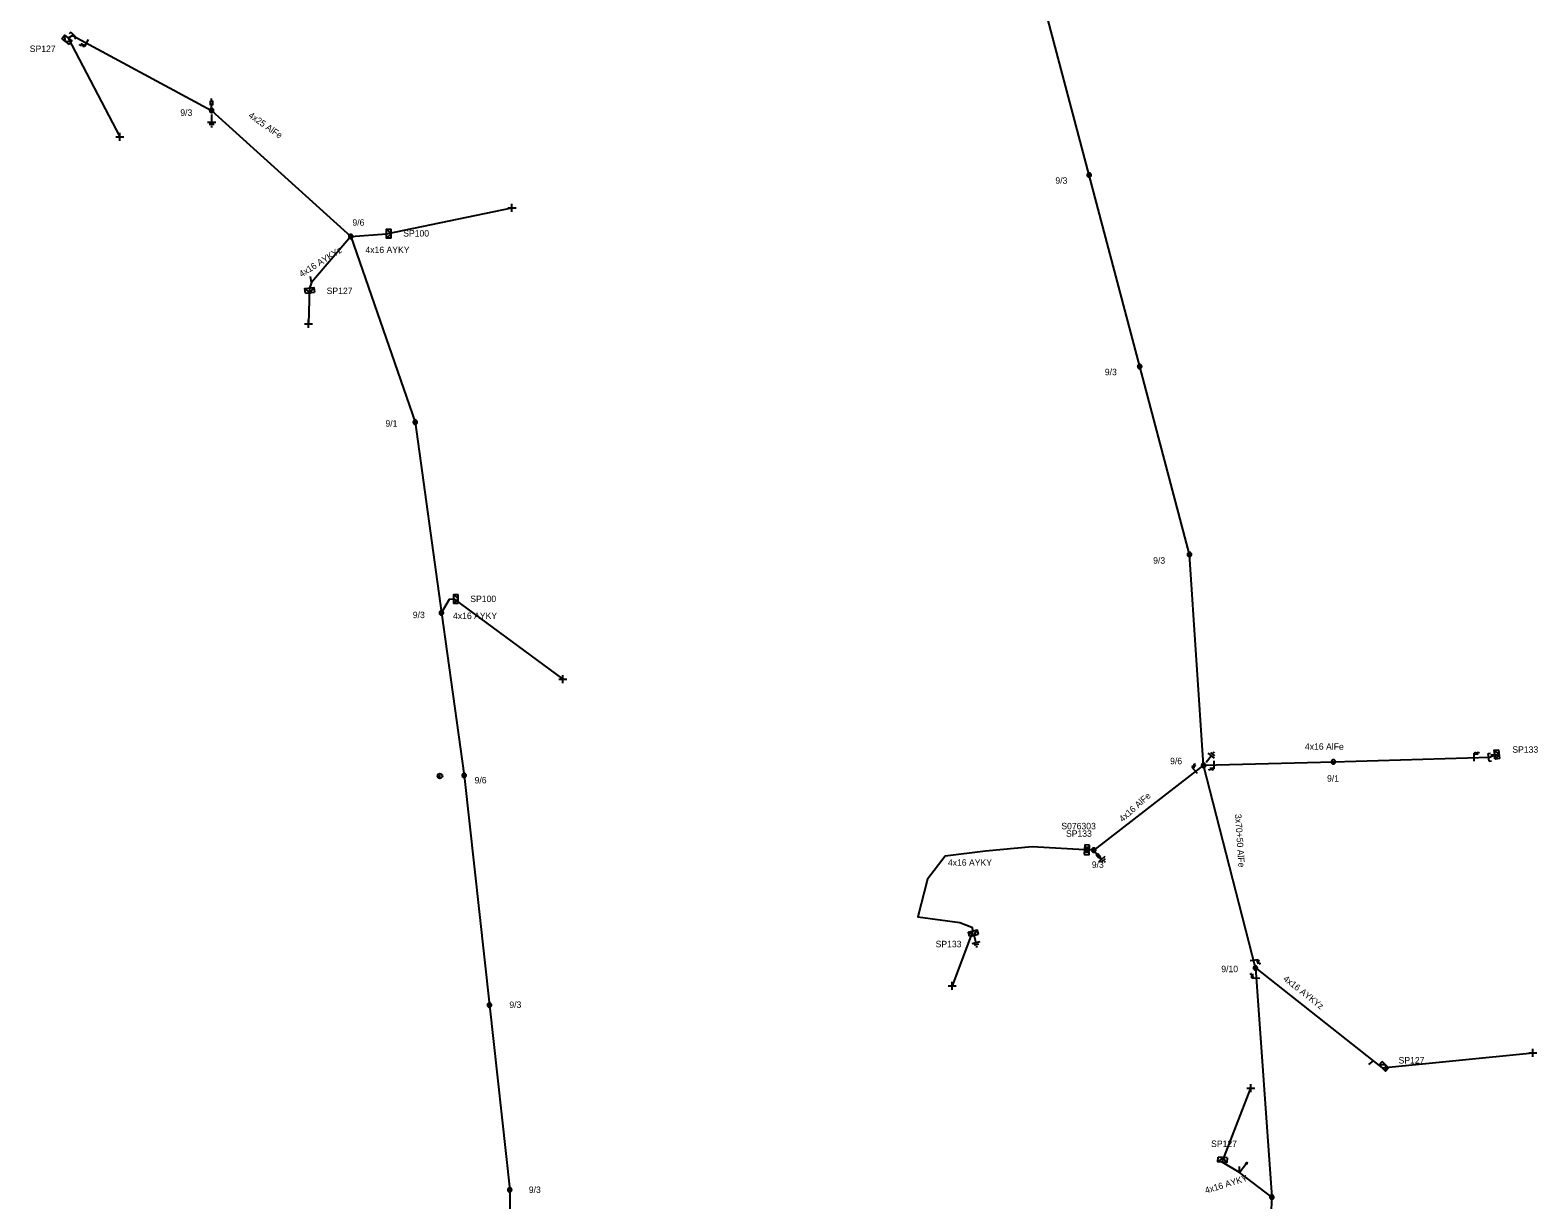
# Model space of a CAD drawing. Extents: x -717562 to -713845, y -1151196 to -1143903.
# Drawn here: x -714412.7 to -714178.8, y -1146157.4 to -1145975.9 of the extents above; entities that cross this region are included whole.
import ezdxf

# ---------------------------------------------------------------- set-up
doc = ezdxf.new("R2010")
doc.units = 0
for name, color, linetype in [('Vrstva 1', 7, 'Continuous'), ('Vrstva 10', 7, 'Continuous'), ('Vrstva 12', 7, 'Continuous'), ('Vrstva 13', 7, 'Continuous'), ('Vrstva 14', 7, 'Continuous'), ('Vrstva 15', 7, 'Continuous'), ('Vrstva 16', 7, 'Continuous'), ('Vrstva 18', 7, 'Continuous'), ('Vrstva 2', 7, 'Continuous'), ('Vrstva 28', 7, 'Continuous'), ('Vrstva 29', 7, 'Continuous'), ('Vrstva 30', 7, 'Continuous'), ('Vrstva 31', 7, 'Continuous'), ('Vrstva 33', 7, 'Continuous'), ('Vrstva 34', 7, 'Continuous'), ('Vrstva 36', 7, 'Continuous'), ('Vrstva 4', 7, 'Continuous'), ('Vrstva 5', 7, 'Continuous'), ('Vrstva 52', 7, 'Continuous'), ('Vrstva 53', 7, 'Continuous'), ('Vrstva 54', 7, 'Continuous'), ('Vrstva 55', 7, 'Continuous'), ('Vrstva 59', 7, 'Continuous'), ('Vrstva 6', 7, 'Continuous'), ('Vrstva 8', 7, 'Continuous'), ('Vrstva 9', 7, 'Continuous')]:
    doc.layers.add(name, color=color, linetype=linetype)

# ---------------------------------------------------------------- blocks, each defined once
blk = doc.blocks.new('NN440')
at = {"layer": 'Vrstva 2'}
for points in [[(0.63, 0), (0.63, 0.06), (0.62, 0.13), (0.6, 0.19), (0.58, 0.25), (0.55, 0.31), (0.51, 0.37), (0.47, 0.42), (0.42, 0.46), (0.37, 0.51), (0.32, 0.54), (0.26, 0.57), (0.2, 0.59), (0.13, 0.61), (0.07, 0.62), (0, 0.63), (-0.06, 0.62), (-0.13, 0.61), (-0.19, 0.59), (-0.26, 0.57), (-0.31, 0.54), (-0.37, 0.51), (-0.42, 0.46), (-0.47, 0.42), (-0.51, 0.37), (-0.54, 0.31), (-0.57, 0.25), (-0.6, 0.19), (-0.62, 0.13), (-0.63, 0.06), (-0.63, 0), (-0.63, -0.07), (-0.62, -0.14), (-0.6, -0.2), (-0.57, -0.26), (-0.54, -0.32), (-0.51, -0.37), (-0.47, -0.43), (-0.42, -0.47), (-0.37, -0.51), (-0.31, -0.55), (-0.26, -0.58), (-0.19, -0.6), (-0.13, -0.62), (-0.06, -0.63), (0, -0.63), (0.07, -0.63), (0.13, -0.62), (0.2, -0.6), (0.26, -0.58), (0.32, -0.55), (0.37, -0.51), (0.42, -0.47), (0.47, -0.43), (0.51, -0.37), (0.55, -0.32), (0.58, -0.26), (0.6, -0.2), (0.62, -0.14), (0.63, -0.07), (0.63, 0)], [(-0.63, 0), (0.63, 0)], [(-0.6, -0.18), (0.57, -0.18)], [(-0.51, -0.32), (0.5, -0.32)], [(-0.37, -0.47), (0.35, -0.47)]]:
    blk.add_lwpolyline(points, dxfattribs=at)
blk = doc.blocks.new('NN560')
at = {"layer": 'Vrstva 2'}
for points in [[(2, 0), (1.59, 0.14)], [(0, 0), (2, 0)], [(2, 0), (1.59, -0.13)]]:
    blk.add_lwpolyline(points, dxfattribs=at)
blk = doc.blocks.new('NN840')
at = {"layer": 'Vrstva 15'}
for points in [[(0, 0.62), (0, -0.63)], [(-0.75, -0.71), (-0.75, -0.66)], [(-0.73, -0.76), (-0.75, -0.71)], [(-0.66, -0.8), (-0.73, -0.76)], [(-0.63, -0.8), (-0.66, -0.8)], [(-0.56, -0.76), (-0.63, -0.8)], [(-0.54, -0.71), (-0.56, -0.76)], [(-0.54, -0.38), (-0.54, -0.71)], [(-0.33, -0.38), (-0.33, -0.8)], [(-0.33, -0.64), (-0.13, -0.38)], [(-0.26, -0.56), (-0.09, -0.8)]]:
    blk.add_lwpolyline(points, dxfattribs=at)
blk = doc.blocks.new('NN770')
at = {"layer": 'Vrstva 10'}
for p, q in [((0, 0.19), (0, 0.26)), ((0, -0.28), (0, 0.11))]:
    blk.add_line(p, q, dxfattribs=at)
blk.add_circle((0, -0.01), 0.375, dxfattribs=at)
blk = doc.blocks.new('NN800')
at = {"layer": 'Vrstva 1'}
for points in [[(-0.44, 0.44), (0.44, -0.44)], [(-0.44, -0.44), (0.44, 0.44)]]:
    blk.add_lwpolyline(points, dxfattribs=at)
blk = doc.blocks.new('NN820')
at = {"layer": 'Vrstva 13'}
for points in [[(0, 0), (0, -1.05)], [(-0.16, -0.81), (0.16, -0.81)], [(-0.16, -1.47), (-0.16, -0.81)], [(0.16, -1.47), (-0.16, -1.47)], [(0, -1.05), (-0.06, -0.93)], [(0, -1.05), (0.06, -0.93)], [(0, -1.47), (0, -1.87)], [(0.16, -0.81), (0.16, -1.47)]]:
    blk.add_lwpolyline(points, dxfattribs=at)
blk = doc.blocks.new('NN620')
at = {"layer": 'Vrstva 8'}
for points in [[(0.75, 0), (-0.75, 0)], [(-0.75, 0), (-0.75, -0.75)], [(0.75, -0.75), (0.75, 0)], [(-0.75, -0.75), (0.75, -0.75)], [(0.37, -0.18), (-0.38, -0.18)], [(-0.38, -0.18), (-0.38, -0.56)], [(-0.38, -0.56), (0.37, -0.56)], [(0.32, -0.23), (-0.33, -0.23)], [(-0.33, -0.23), (-0.33, -0.51)], [(-0.33, -0.51), (0.32, -0.51)], [(0.27, -0.27), (-0.28, -0.27)], [(-0.28, -0.27), (-0.28, -0.46)], [(-0.28, -0.46), (0.27, -0.46)], [(0.23, -0.32), (-0.23, -0.32)], [(-0.23, -0.32), (-0.23, -0.42)], [(-0.23, -0.42), (0.23, -0.42)], [(-0.19, -0.37), (0.19, -0.37)], [(0.23, -0.42), (0.23, -0.32)], [(0.27, -0.46), (0.27, -0.27)], [(0.32, -0.51), (0.32, -0.23)], [(0.37, -0.56), (0.37, -0.18)]]:
    blk.add_lwpolyline(points, dxfattribs=at)
blk = doc.blocks.new('NN630')
at = {"layer": 'Vrstva 9'}
for points in [[(0, -0.7), (-0.7, 0)], [(-0.7, -0.7), (-0.7, 0), (0.7, 0), (0.7, -0.7)], [(-0.7, -0.7), (0.7, -0.7)], [(0, -0.7), (0.7, 0)]]:
    blk.add_lwpolyline(points, dxfattribs=at)
blk = doc.blocks.new('NN810')
at = {"layer": 'Vrstva 14'}
for points in [[(0.63, -1.89), (-0.62, -1.89)], [(0.39, -2.2), (-0.4, -2.2)], [(0, -0.64), (0, -1.89)], [(0, -2.52), (-0.12, -2.52)], [(0.14, -2.52), (0, -2.52)]]:
    blk.add_lwpolyline(points, dxfattribs=at)
blk = doc.blocks.new('NN510')
at = {"layer": 'Vrstva 2'}
blk.add_lwpolyline([(0, 0), (0, 0.94)], dxfattribs=at)
blk = doc.blocks.new('NN515')
at = {"layer": 'Vrstva 2'}
for points in [[(-0.59, 0.18), (0.59, 0.18)], [(-0.59, 0.18), (-0.59, -0.18)], [(0.59, 0.18), (0.59, -0.18)]]:
    blk.add_lwpolyline(points, dxfattribs=at)

msp = doc.modelspace()

# ---------------------------------------------------------------- linework, layer by layer
at = {"layer": 'Vrstva 1'}
for points in [[(-714230.62, -1146090.01), (-714232.82, -1146057.29), (-714240.54, -1146028.12), (-714248.38, -1145998.41), (-714256.18, -1145968.88), (-714269.83, -1145931.83), (-714277.28, -1145901.51), (-714284.27, -1145873.27)], [(-714406.11, -1145976.77), (-714384.55, -1145988.39), (-714362.95, -1146007.94), (-714352.95, -1146036.78), (-714348.89, -1146066.34), (-714345.36, -1146091.58), (-714341.44, -1146127.21), (-714338.29, -1146155.88), (-714338.36, -1146187.53), (-714327.11, -1146208.38), (-714313.96, -1146230.67), (-714316.92, -1146251.17), (-714323.14, -1146275.38), (-714326.25, -1146303.02)], [(-714230.62, -1146090.01), (-714247.67, -1146103.16)], [(-714222.58, -1146121.46), (-714230.62, -1146090.01)], [(-714222.58, -1146121.46), (-714220.03, -1146157.01), (-714221.53, -1146184), (-714216.8, -1146210.17)]]:
    msp.add_lwpolyline(points, dxfattribs=at)
at = {"layer": 'Vrstva 4'}
msp.add_lwpolyline([(-714230.62, -1146090.01), (-714210.49, -1146089.46), (-714186.22, -1146088.74), (-714185.44, -1146088.37)], dxfattribs=at)
at = {"layer": 'Vrstva 5'}
msp.add_lwpolyline([(-714247.67, -1146103.16), (-714248.4, -1146103.14)], dxfattribs=at)
at = {"layer": 'Vrstva 52'}
for points in [[(-714406.11, -1145976.77), (-714406.8, -1145977.16)], [(-714362.95, -1146007.94), (-714357.39, -1146007.52)], [(-714348.89, -1146066.34), (-714347.62, -1146064.22), (-714346.98, -1146064.2)], [(-714249.1, -1146103.11), (-714257.2, -1146102.66), (-714264.46, -1146103.33), (-714270.71, -1146104.09), (-714273.49, -1146107.7), (-714274.95, -1146113.51), (-714268.45, -1146114.38), (-714266.6, -1146115.15), (-714266.44, -1146115.71)], [(-714220.03, -1146157.01), (-714225.06, -1146153.19), (-714227.72, -1146151.58)]]:
    msp.add_lwpolyline(points, dxfattribs=at)
at = {"layer": 'Vrstva 54'}
for points in [[(-714362.95, -1146007.94), (-714369.04, -1146015.07), (-714369.38, -1146015.96)], [(-714222.58, -1146121.46), (-714204.32, -1146135.84), (-714202.9, -1146136.96)]]:
    msp.add_lwpolyline(points, dxfattribs=at)
at = {"layer": 'Vrstva 59'}
for points in [[(-714406.8, -1145977.16), (-714398.81, -1145992.5)], [(-714357.39, -1146007.52), (-714337.94, -1146003.5)], [(-714369.38, -1146015.96), (-714369.5, -1146021.51)], [(-714346.98, -1146064.2), (-714330.06, -1146076.63)], [(-714266.44, -1146115.71), (-714269.63, -1146124.25)], [(-714202.9, -1146136.96), (-714179.56, -1146134.63)], [(-714227.72, -1146151.58), (-714223.31, -1146140.13)]]:
    msp.add_lwpolyline(points, dxfattribs=at)

# ---------------------------------------------------------------- block references
at = {"layer": 'Vrstva 13'}
for name, p, rotation in [('NN515', (-714406.11, -1145976.77), -43.851980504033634), ('NN510', (-714369.04, -1146015.07), 8.623150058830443), ('NN515', (-714186.22, -1146088.74), 96.41968054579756), ('NN510', (-714204.32, -1146135.84), 129.76348881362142), ('NN560', (-714225.05, -1146153.2), 52.7640110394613)]:
    msp.add_blockref(name, p, dxfattribs=dict(at, rotation=rotation))
for p, xscale, yscale, rotation in [((-714384.55, -1145988.39), 0.5, 0.5, -28.320583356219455), ((-714248.38, -1145998.41), 0.5000000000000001, 0.4999999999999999, -75.20793339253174), ((-714362.95, -1146007.94), 0.5, 0.5, -35.069177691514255), ((-714240.54, -1146028.12), 0.5, 0.5, -75.20793335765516), ((-714352.95, -1146036.78), 0.5, 0.5, -90), ((-714232.82, -1146057.29), 0.5, 0.5, -75.20793335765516), ((-714348.89, -1146066.34), 0.5, 0.5, -82.03311946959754), ((-714230.62, -1146090.01), 0.5, 0.5000000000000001, -86.0199166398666), ((-714210.49, -1146089.46), 0.49999999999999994, 0.4999999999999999, 0.7188222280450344), ((-714345.36, -1146091.58), 0.49999999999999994, 0.5, -82.03311940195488), ((-714247.67, -1146103.16), 0.5000000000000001, 0.5000000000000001, 41.93301390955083), ((-714222.58, -1146121.46), 0.5, 0.5000000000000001, -86.0199166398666), ((-714341.44, -1146127.21), 0.5, 0.5, -83.72445830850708), ((-714338.29, -1146155.88), 0.5, 0.5, -83.72445830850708), ((-714220.03, -1146157.01), 0.5000000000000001, 0.5, -86.58503612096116)]:
    msp.add_blockref('NN440', p, dxfattribs=dict(at, xscale=xscale, yscale=yscale, rotation=rotation))
msp.add_blockref('NN510', (-714225.05, -1146153.2), dxfattribs=at)
at = {"layer": 'Vrstva 15'}
msp.add_blockref('NN810', (-714384.55, -1145988.39), dxfattribs=at)
for p, rotation in [((-714230.62, -1146090.01), 141.66196388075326), ((-714247.67, -1146103.16), 41.933013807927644), ((-714266.44, -1146115.71), 14.036244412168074)]:
    msp.add_blockref('NN810', p, dxfattribs=dict(at, rotation=rotation))
at = {"layer": 'Vrstva 16'}
for p, rotation in [((-714384.55, -1145988.39), 180), ((-714247.67, -1146103.16), 37.643708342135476)]:
    msp.add_blockref('NN820', p, dxfattribs=dict(at, rotation=rotation))
at = {"layer": 'Vrstva 18'}
for p, rotation in [((-714403.98, -1145977.91), -28.319608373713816), ((-714229.04, -1146089.95), 0.7193222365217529), ((-714188.65, -1146088.77), -179.28159444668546), ((-714232, -1146090.84), -138.06833618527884), ((-714222.77, -1146120.21), 98.31473609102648), ((-714222.52, -1146123.07), -90.79369719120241)]:
    msp.add_blockref('NN840', p, dxfattribs=dict(at, rotation=rotation))
at = {"layer": 'Vrstva 28', "rotation": 86.9966805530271}
msp.add_blockref('NN620', (-714249.1, -1146103.11), dxfattribs=at)
at = {"layer": 'Vrstva 31'}
for p, rotation in [((-714406.8, -1145977.16), -37.334130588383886), ((-714357.39, -1146007.52), 90), ((-714369.38, -1146015.96), 6.99074168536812), ((-714346.98, -1146064.2), 90), ((-714185.44, -1146088.37), 97.50473326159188), ((-714266.44, -1146115.71), 14.03624454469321), ((-714202.9, -1146136.96), 135), ((-714227.72, -1146151.58), 175.53986680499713)]:
    msp.add_blockref('NN630', p, dxfattribs=dict(at, rotation=rotation))
at = {"layer": 'Vrstva 34'}
for p, rotation in [((-714398.81, -1145992.5), 45), ((-714337.94, -1146003.5), 44.99999995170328), ((-714369.5, -1146021.51), 45), ((-714330.06, -1146076.63), 45), ((-714185.44, -1146088.37), 45), ((-714269.63, -1146124.25), 45), ((-714179.56, -1146134.63), 45), ((-714223.31, -1146140.13), 45)]:
    msp.add_blockref('NN800', p, dxfattribs=dict(at, rotation=rotation))
at = {"layer": 'Vrstva 36'}
msp.add_blockref('NN770', (-714349.12, -1146091.65), dxfattribs=at)

# ---------------------------------------------------------------- texts
at = {"layer": 'Vrstva 12'}
for s, p in [('9/3', (-714389.41, -1145989.23)), ('9/3', (-714253.62, -1145999.76)), ('9/6', (-714362.7, -1146006.28)), ('9/3', (-714245.95, -1146029.48)), ('9/1', (-714357.58, -1146037.46)), ('9/3', (-714238.45, -1146058.72)), ('9/3', (-714353.33, -1146067.17)), ('9/6', (-714235.82, -1146089.84)), ('9/6', (-714343.74, -1146092.82)), ('9/1', (-714211.47, -1146092.54)), ('9/3', (-714247.97, -1146105.92)), ('9/10', (-714227.88, -1146122.11)), ('9/3', (-714338.35, -1146127.66)), ('9/3', (-714335.33, -1146156.37))]:
    msp.add_text(s, height=1, dxfattribs=at).set_placement(p)
at = {"layer": 'Vrstva 2'}
for s, rotation, p in [('4x25 AlFe', 325.042, (-714378.94, -1145989.37)), ('4x16 AlFe', 41.933, (-714243.2, -1146098.88)), ('3x70+50 AlFe', 273.803, (-714225.76, -1146097.6))]:
    msp.add_text(s, height=1, rotation=rotation, dxfattribs=at).set_placement(p)
at = {"layer": 'Vrstva 29'}
msp.add_text('S076303', height=1, dxfattribs=at).set_placement((-714252.7, -1146099.94))
at = {"layer": 'Vrstva 30'}
msp.add_text('SP133', height=1, dxfattribs=at).set_placement((-714251.98, -1146101.1))
at = {"layer": 'Vrstva 33'}
for s, p in [('SP127', (-714412.77, -1145979.32)), ('SP100', (-714354.82, -1146007.96)), ('SP127', (-714366.7, -1146016.89)), ('SP100', (-714344.41, -1146064.68)), ('SP133', (-714182.72, -1146088.06)), ('SP133', (-714272.21, -1146118.24)), ('SP127', (-714200.37, -1146136.28)), ('SP127', (-714229.46, -1146149.23))]:
    msp.add_text(s, height=1, dxfattribs=at).set_placement(p)
at = {"layer": 'Vrstva 53'}
msp.add_text('4x16 AlFe', height=1, rotation=359.837, dxfattribs=at).set_placement((-714214.9, -1146087.59))
at = {"layer": 'Vrstva 54'}
for p in [(-714360.68, -1146010.52), (-714347.09, -1146067.31), (-714270.3, -1146105.6)]:
    msp.add_text('4x16 AYKY', height=1, dxfattribs=at).set_placement(p)
msp.add_text('4x16 AYKY', height=1, rotation=16.912, dxfattribs=at).set_placement((-714230.25, -1146156.48))
at = {"layer": 'Vrstva 55'}
for rotation, p in [(32.219, (-714370.58, -1146014.31)), (321.771, (-714218.37, -1146123.3))]:
    msp.add_text('4x16 AYKYz', height=1, rotation=rotation, dxfattribs=at).set_placement(p)
at = {"layer": 'Vrstva 6'}
msp.add_text('4x16 AYKY', height=1, dxfattribs=at).set_placement((-714270.3, -1146105.6))

doc.saveas('drawing.dxf')
